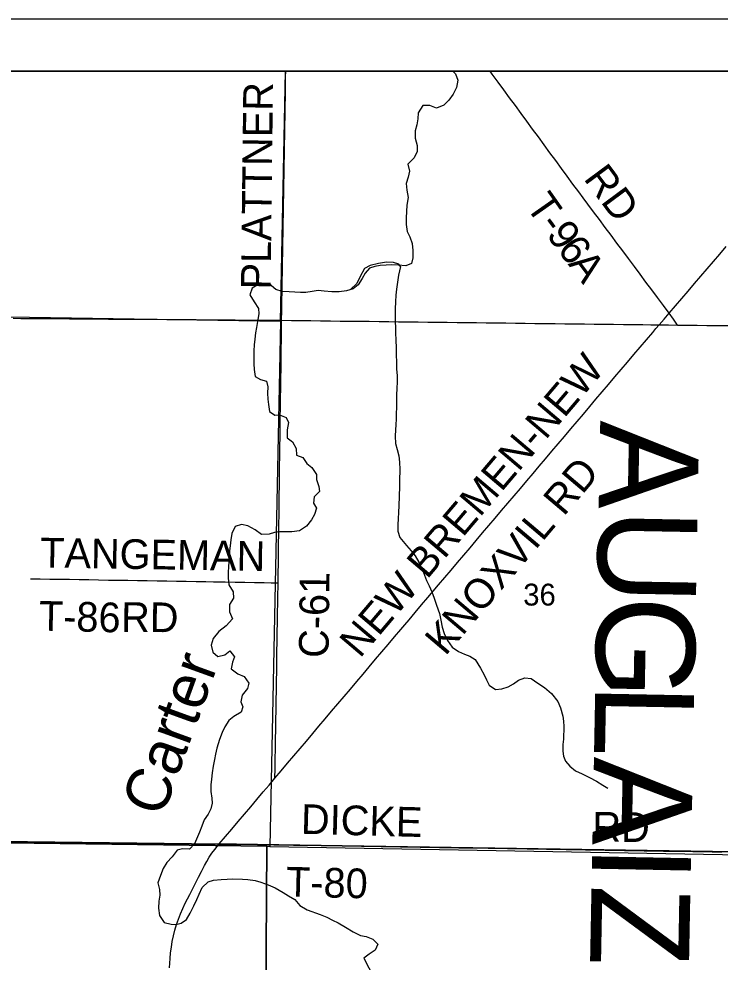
# Model space of a CAD drawing. Extents: x 0 to 34, y 0 to 22.
# Drawn here: x 6.316 to 7.658, y 19.194 to 21 of the extents above; entities that cross this region are included whole.
import ezdxf

# ---------------------------------------------------------------- set-up
doc = ezdxf.new("R2010")
doc.units = 0
for name, color, linetype in [('GM_X_Corporation', 7, 'Continuous'), ('GM_X_County_Road', 7, 'Continuous'), ('GM_X_County_Road_Text', 7, 'Continuous'), ('GM_X_County_Text', 7, 'Continuous'), ('GM_X_Minor_River', 7, 'Continuous'), ('GM_X_Minor_River_Text', 7, 'Continuous'), ('GM_X_Section_Text', 7, 'Continuous'), ('GM_X_Township_Road', 7, 'Continuous'), ('GM_X_Township_Road_Text', 7, 'Continuous'), ('SH_Data', 7, 'Continuous')]:
    doc.layers.add(name, color=color, linetype=linetype)

msp = doc.modelspace()

# ---------------------------------------------------------------- linework, layer by layer
at = {"layer": 'GM_X_Corporation'}
for points in [[(8.9, 20.9), (2.1, 20.9)], [(7.8362, 20.9), (2.1, 20.9)], [(7.8062, 19.1933), (7.8077, 19.2659), (7.8087, 19.3138), (7.8096, 19.3604), (7.8106, 19.4031), (6.935, 19.4163), (6.733, 19.4196), (6.6989, 19.42), (5.8089, 19.4308), (5.2195, 19.4431), (4.8049, 19.4497), (4.7562, 19.4505)], [(5.8089, 19.4308), (6.6989, 19.42), (6.733, 19.4196), (6.935, 19.4163), (7.8106, 19.4031)]]:
    msp.add_lwpolyline(points, dxfattribs=at)
for points in [[(6.8262, 20.9), (5.8246, 20.9), (5.8161, 20.437), (6.817, 20.4215)], [(5.8161, 20.437), (6.817, 20.4215), (6.7967, 19.4154), (6.7907, 19.4159), (5.8008, 19.4289)], [(5.8008, 19.4289), (6.7907, 19.4159), (6.7843, 18.4413), (5.7966, 18.4409)], [(6.7967, 19.4154), (7.8071, 19.3973), (7.7914, 18.4475), (7.7907, 18.396), (6.7843, 18.4413), (6.7907, 19.4159)]]:
    msp.add_lwpolyline(points, close=True, dxfattribs=at)
at = {"layer": 'GM_X_County_Road'}
for points in [[(6.8063, 19.5461), (6.8066, 19.5648), (6.8069, 19.5834), (6.8072, 19.6021), (6.8075, 19.6207), (6.8078, 19.6393), (6.8081, 19.658), (6.8084, 19.6766), (6.8087, 19.6953), (6.809, 19.7139), (6.8093, 19.7325), (6.8096, 19.7512), (6.8099, 19.7698), (6.8102, 19.7885), (6.8105, 19.8071), (6.8108, 19.8257), (6.8111, 19.8444), (6.8114, 19.863), (6.8117, 19.8817), (6.812, 19.9003), (6.8122, 19.9103), (6.8123, 19.9202), (6.8126, 19.9388), (6.8128, 19.9575), (6.8131, 19.9761), (6.8133, 19.9948), (6.8136, 20.0134), (6.8138, 20.032), (6.8141, 20.0507), (6.8143, 20.0693), (6.8146, 20.088), (6.8148, 20.1066), (6.8151, 20.1252), (6.8153, 20.1439), (6.8156, 20.1625), (6.8159, 20.1812), (6.8161, 20.1998), (6.8164, 20.2185), (6.8166, 20.2371), (6.8169, 20.2557), (6.8171, 20.2744), (6.8174, 20.293), (6.8176, 20.3117), (6.8179, 20.3303), (6.8181, 20.3489), (6.8184, 20.3676), (6.8186, 20.3862), (6.8189, 20.4046), (6.8191, 20.4229), (6.8194, 20.4415), (6.8197, 20.4602), (6.82, 20.4788), (6.8204, 20.4975), (6.8207, 20.5161), (6.821, 20.5347), (6.8213, 20.5534), (6.8216, 20.572), (6.8219, 20.5907), (6.8222, 20.6093), (6.8225, 20.628), (6.8228, 20.6466), (6.8231, 20.6652), (6.8235, 20.6839), (6.8238, 20.7025), (6.8241, 20.7212), (6.8244, 20.7398), (6.8247, 20.7584), (6.825, 20.7771), (6.8253, 20.7957), (6.8256, 20.8144), (6.8259, 20.833), (6.8262, 20.8516), (6.8265, 20.8703), (6.8268, 20.8889), (6.827, 20.9)], [(6.6996, 19.4202), (6.7116, 19.4344), (6.7237, 19.4487), (6.7358, 19.4629), (6.7478, 19.4771), (6.7599, 19.4913), (6.7719, 19.5056), (6.784, 19.5198), (6.7951, 19.533), (6.8063, 19.5461), (6.8183, 19.5604), (6.8304, 19.5746), (6.8424, 19.5888), (6.8545, 19.603), (6.8665, 19.6173), (6.8786, 19.6315), (6.8906, 19.6457), (6.9026, 19.66), (6.9147, 19.6742), (6.9267, 19.6884), (6.9388, 19.7027), (6.9508, 19.7169), (6.9628, 19.7311), (6.9749, 19.7453), (6.9869, 19.7596), (6.999, 19.7738), (7.011, 19.788), (7.023, 19.8023), (7.0351, 19.8165), (7.0471, 19.8307), (7.055, 19.84), (7.0629, 19.8494), (7.0749, 19.8636), (7.087, 19.8778), (7.099, 19.8921), (7.1092, 19.9041), (7.1194, 19.9161), (7.1314, 19.9304), (7.1435, 19.9446), (7.1555, 19.9588), (7.1675, 19.973), (7.1796, 19.9873), (7.1916, 20.0015), (7.2037, 20.0157), (7.2157, 20.0299), (7.2278, 20.0442), (7.2398, 20.0584), (7.2519, 20.0726), (7.264, 20.0868), (7.276, 20.101), (7.2881, 20.1153), (7.3001, 20.1295), (7.3122, 20.1437), (7.3242, 20.1579), (7.3363, 20.1722), (7.3483, 20.1864), (7.3604, 20.2006), (7.3724, 20.2148), (7.3845, 20.2291), (7.3965, 20.2433), (7.4086, 20.2575), (7.4206, 20.2717), (7.4327, 20.286), (7.4447, 20.3002), (7.4568, 20.3144), (7.4689, 20.3286), (7.4809, 20.3428), (7.493, 20.3571), (7.505, 20.3713), (7.5171, 20.3855), (7.5291, 20.3997), (7.5352, 20.4069), (7.5413, 20.4141), (7.5511, 20.4252), (7.5608, 20.4363), (7.5729, 20.4505), (7.5851, 20.4646), (7.5972, 20.4788), (7.6093, 20.493), (7.6214, 20.5072), (7.6335, 20.5213), (7.6456, 20.5355), (7.6577, 20.5497), (7.6698, 20.5639)], [(6.6047, 19.1828), (6.6058, 19.2009), (6.6067, 19.2119), (6.6081, 19.2228), (6.6099, 19.2337), (6.6122, 19.2446), (6.6149, 19.2553), (6.618, 19.2659), (6.6216, 19.2763), (6.6256, 19.2866), (6.63, 19.2968), (6.6348, 19.3067), (6.6432, 19.3233), (6.6517, 19.34), (6.6601, 19.3566), (6.6658, 19.3677), (6.6715, 19.3788), (6.6758, 19.3869), (6.6805, 19.3948), (6.6856, 19.4024), (6.691, 19.4098), (6.6996, 19.4202)]]:
    msp.add_lwpolyline(points, dxfattribs=at)
at = {"layer": 'GM_X_Minor_River'}
for points in [[(7.1466, 20.9), (7.1516, 20.8946), (7.1562, 20.8827), (7.1536, 20.8683), (7.1472, 20.8556), (7.1389, 20.8444), (7.1292, 20.8348), (7.1154, 20.8291), (7.1026, 20.834), (7.0893, 20.834), (7.0806, 20.8198), (7.0799, 20.8088), (7.0777, 20.7971), (7.0748, 20.7858), (7.0744, 20.7713), (7.0782, 20.7576), (7.0786, 20.7462), (7.0726, 20.7342), (7.0605, 20.7216), (7.0636, 20.7086), (7.0614, 20.6966), (7.0577, 20.6845), (7.0585, 20.6723), (7.0615, 20.6582)], [(7.0615, 20.6582), (7.0585, 20.6435), (7.0578, 20.6314), (7.0571, 20.6189), (7.0571, 20.606), (7.0594, 20.5926), (7.0641, 20.5826), (7.0687, 20.5696), (7.0702, 20.5563), (7.0702, 20.5423), (7.0676, 20.5313), (7.0565, 20.5274), (7.0418, 20.5282), (7.03, 20.5289), (7.0194, 20.5284), (7.0076, 20.5276), (6.9973, 20.5259), (6.9874, 20.5228), (6.9791, 20.5131), (6.9732, 20.503), (6.9657, 20.4907), (6.956, 20.4834), (6.943, 20.4792), (6.9289, 20.4773), (6.9152, 20.4776), (6.9008, 20.4788), (6.8887, 20.4798), (6.8777, 20.4782), (6.8651, 20.4763), (6.8552, 20.4758), (6.8446, 20.4768), (6.8333, 20.4771), (6.8204, 20.4782), (6.808, 20.4819), (6.795, 20.4925), (6.7851, 20.4935), (6.7756, 20.4919), (6.7625, 20.4846), (6.7584, 20.4715), (6.7668, 20.4584), (6.7748, 20.4452), (6.7756, 20.4354), (6.7734, 20.4244), (6.7708, 20.4089), (6.7693, 20.3987), (6.7679, 20.3866), (6.7665, 20.3756), (6.7658, 20.3643), (6.7658, 20.3506), (6.7659, 20.3396), (6.7667, 20.3286), (6.7683, 20.3153), (6.7784, 20.3097), (6.7904, 20.3063), (6.7924, 20.2956), (6.7921, 20.2831), (6.7926, 20.2721), (6.7938, 20.2615), (6.7957, 20.2481), (6.8058, 20.2414), (6.8153, 20.2419), (6.8277, 20.237), (6.8323, 20.2271), (6.8297, 20.2131), (6.83, 20.1979), (6.8401, 20.19), (6.8469, 20.1773), (6.8478, 20.1648), (6.8598, 20.1599), (6.8674, 20.1487), (6.8771, 20.1409), (6.8859, 20.1278), (6.8856, 20.1183), (6.8902, 20.1049), (6.8918, 20.0953), (6.8813, 20.0846), (6.8798, 20.0729), (6.8857, 20.0629), (6.8823, 20.0512), (6.8763, 20.0411), (6.8665, 20.0285), (6.8534, 20.0197), (6.8386, 20.0178), (6.8283, 20.0177), (6.8154, 20.018), (6.8055, 20.0168), (6.7952, 20.0136), (6.7807, 20.0125), (6.7685, 20.0215), (6.7546, 20.0291), (6.7422, 20.0317), (6.7303, 20.0282), (6.7235, 20.0147), (6.7217, 20.0023), (6.7206, 19.9913), (6.7196, 19.9814), (6.719, 19.9712), (6.7179, 19.9602), (6.7177, 19.9508), (6.717, 19.9405), (6.7167, 19.9295)], [(7.0465, 20.5261), (7.0433, 20.5301), (7.0332, 20.5334), (7.0199, 20.5341), (7.0043, 20.5318), (6.9883, 20.5277), (6.9775, 20.5219), (6.9695, 20.5069), (6.9631, 20.4931), (6.951, 20.482)], [(7.0465, 20.5261), (7.0428, 20.5092), (7.0409, 20.4956), (7.039, 20.4827), (7.0376, 20.471), (7.0369, 20.4585), (7.0365, 20.4449), (7.0366, 20.4319), (7.0366, 20.4202), (7.0371, 20.4092), (7.0372, 20.3989), (7.0376, 20.3845), (7.0383, 20.3704), (7.0384, 20.3575), (7.0387, 20.342), (7.0392, 20.3298), (7.0399, 20.3165), (7.04, 20.3036), (7.0397, 20.2934), (7.0389, 20.2786), (7.039, 20.2661), (7.0382, 20.2342), (7.0375, 20.2225), (7.0368, 20.213), (7.0361, 20.2009), (7.0373, 20.1872), (7.04, 20.1753), (7.0435, 20.1631), (7.0447, 20.1509), (7.0451, 20.1373), (7.0445, 20.116), (7.0446, 20.1046), (7.0436, 20.0678), (7.0429, 20.0553), (7.0418, 20.0425), (7.0415, 20.0319), (7.0416, 20.0193), (7.045, 20.0067), (7.0579, 19.9916), (7.0667, 19.9815), (7.0745, 19.9718), (7.0817, 19.9595), (7.0864, 19.9495), (7.0903, 19.9399), (7.0964, 19.9249), (7.1014, 19.9145), (7.1064, 19.9027), (7.111, 19.8908), (7.1156, 19.8774), (7.1209, 19.8617), (7.1239, 19.8487), (7.1266, 19.8353), (7.1301, 19.8231), (7.1362, 19.8097), (7.1457, 19.7973), (7.1576, 19.7886), (7.1693, 19.7837), (7.179, 19.7797), (7.1895, 19.7734), (7.1997, 19.7568), (7.2065, 19.7441), (7.2108, 19.7345), (7.2162, 19.7241), (7.2286, 19.7162), (7.2407, 19.7174), (7.2526, 19.7209), (7.2626, 19.727), (7.2726, 19.7336), (7.2845, 19.7382), (7.2963, 19.7372), (7.3093, 19.7281), (7.322, 19.7198), (7.3357, 19.7084), (7.3478, 19.6929), (7.3528, 19.6807), (7.3573, 19.6646), (7.3586, 19.6551), (7.3591, 19.6448), (7.3584, 19.6206), (7.3574, 19.6107), (7.3571, 19.5978), (7.3587, 19.5883), (7.3626, 19.5787), (7.3704, 19.569), (7.3815, 19.5604), (7.3942, 19.5543), (7.4085, 19.5475), (7.4216, 19.5404), (7.4339, 19.5328), (7.4436, 19.5269)], [(6.7167, 19.9295), (6.7183, 19.9162), (6.7263, 19.9031), (6.7271, 19.8909), (6.7195, 19.8786), (6.7192, 19.8646), (6.7253, 19.8511), (6.7128, 19.8378), (6.6992, 19.8272), (6.6882, 19.8134), (6.6841, 19.8006), (6.6875, 19.7872), (6.6972, 19.7794), (6.7102, 19.7825), (6.7199, 19.7902), (6.7286, 19.7782), (6.725, 19.768), (6.7227, 19.7552), (6.7354, 19.7461), (6.7474, 19.7409), (6.7565, 19.7281), (6.7536, 19.718), (6.7438, 19.7049), (6.7412, 19.6925), (6.7451, 19.6829), (6.7414, 19.6727), (6.7279, 19.664), (6.7182, 19.6566), (6.7107, 19.6447), (6.7055, 19.6338), (6.7002, 19.6203), (6.6948, 19.6034), (6.6926, 19.5924), (6.6908, 19.5818), (6.6882, 19.569), (6.686, 19.5562), (6.6849, 19.5441), (6.6838, 19.5335), (6.6835, 19.5206), (6.6858, 19.508), (6.6859, 19.4981), (6.6834, 19.4872), (6.6782, 19.4774), (6.6711, 19.4662), (6.6666, 19.4542), (6.6621, 19.4429), (6.6524, 19.4204), (6.643, 19.4104), (6.6294, 19.4108), (6.6195, 19.4084), (6.6096, 19.3957), (6.5995, 19.385), (6.5927, 19.373), (6.5871, 19.3595), (6.5825, 19.346), (6.5856, 19.333), (6.5861, 19.3224), (6.5842, 19.3106), (6.5835, 19.2974), (6.5854, 19.2833), (6.5942, 19.2701), (6.6074, 19.2664), (6.6168, 19.2661), (6.6268, 19.2685), (6.6368, 19.2755), (6.644, 19.2874), (6.6512, 19.3017), (6.6568, 19.314), (6.6612, 19.3242), (6.6669, 19.3369), (6.6786, 19.3476), (6.6889, 19.3508), (6.7033, 19.3519), (6.7147, 19.3531), (6.7242, 19.3533), (6.7443, 19.3527), (6.7546, 19.3521), (6.7685, 19.3502), (6.7791, 19.3469), (6.7934, 19.342), (6.8065, 19.3363), (6.8218, 19.3272), (6.8323, 19.3208), (6.8442, 19.3141), (6.8541, 19.3021), (6.868, 19.2941), (6.8928, 19.2851), (6.9055, 19.2798), (6.9164, 19.2746), (6.9273, 19.269), (6.9415, 19.2611), (6.956, 19.252), (6.9703, 19.2451), (6.9808, 19.243), (6.9936, 19.2381), (7.0032, 19.2283), (6.998, 19.2171), (6.9864, 19.2094), (6.9767, 19.2013), (7.0145, 19.1272)]]:
    msp.add_lwpolyline(points, dxfattribs=at)
at = {"layer": 'GM_X_Township_Road'}
for points in [[(7.5768, 20.4137), (7.5688, 20.425), (7.5608, 20.4363), (7.5497, 20.4512), (7.5385, 20.4662), (7.5274, 20.4811), (7.5162, 20.4961), (7.5051, 20.511), (7.494, 20.526), (7.4828, 20.5409), (7.4717, 20.5558), (7.4605, 20.5708), (7.4494, 20.5857), (7.4382, 20.6007), (7.4271, 20.6156), (7.4159, 20.6306), (7.4048, 20.6455), (7.3962, 20.6571), (7.3875, 20.6686), (7.3765, 20.6836), (7.3655, 20.6987), (7.3545, 20.7137), (7.3435, 20.7288), (7.3324, 20.7438), (7.3214, 20.7588), (7.3104, 20.7739), (7.2994, 20.7889), (7.2883, 20.8039), (7.2773, 20.819), (7.2663, 20.834), (7.2553, 20.8491), (7.2442, 20.8641), (7.2332, 20.8791), (7.2222, 20.8942), (7.2179, 20.9)], [(6.3054, 20.4269), (6.3198, 20.4266), (6.3385, 20.4264), (6.3571, 20.4263), (6.3758, 20.4262), (6.3944, 20.426), (6.413, 20.4259), (6.4317, 20.4257), (6.4503, 20.4256), (6.469, 20.4255), (6.4876, 20.4253), (6.5062, 20.4252), (6.5249, 20.4251), (6.5435, 20.4249), (6.5622, 20.4248), (6.5808, 20.4247), (6.5994, 20.4245), (6.6181, 20.4244), (6.6367, 20.4242), (6.6554, 20.4241), (6.674, 20.424), (6.6927, 20.4238), (6.7113, 20.4237), (6.7299, 20.4236), (6.7486, 20.4234), (6.7672, 20.4233), (6.7859, 20.4231), (6.8025, 20.423), (6.8191, 20.4229), (6.8378, 20.4227), (6.8564, 20.4225), (6.875, 20.4222), (6.8937, 20.422), (6.9123, 20.4218), (6.931, 20.4215), (6.9496, 20.4213), (6.9682, 20.4211), (6.9869, 20.4209), (7.0055, 20.4206), (7.0242, 20.4204), (7.0428, 20.4202), (7.0614, 20.42), (7.0801, 20.4197), (7.0987, 20.4195), (7.1174, 20.4193), (7.136, 20.4191), (7.1547, 20.4188), (7.1733, 20.4186), (7.1919, 20.4184), (7.2106, 20.4181), (7.2292, 20.4179), (7.2479, 20.4177), (7.2665, 20.4175), (7.2851, 20.4172), (7.3038, 20.417), (7.3138, 20.4169), (7.3239, 20.4168), (7.3425, 20.4165), (7.3612, 20.4163), (7.3798, 20.4161), (7.3985, 20.4159), (7.4171, 20.4156), (7.4357, 20.4154), (7.4544, 20.4152), (7.473, 20.415), (7.4917, 20.4147), (7.5103, 20.4145), (7.5258, 20.4143), (7.5413, 20.4141)], [(7.5413, 20.4141), (7.5591, 20.4139), (7.5768, 20.4137), (7.5955, 20.4135), (7.6141, 20.4133), (7.6327, 20.4132), (7.6514, 20.413), (7.67, 20.4128), (7.6887, 20.4126), (7.7073, 20.4125), (7.7259, 20.4123), (7.7446, 20.4121), (7.7632, 20.4119), (7.7819, 20.4117), (7.8005, 20.4116), (7.8153, 20.4114), (7.8301, 20.4113)], [(6.3384, 19.9281), (6.3571, 19.9278), (6.3757, 19.9275), (6.3943, 19.9272), (6.413, 19.9269), (6.4316, 19.9266), (6.4503, 19.9263), (6.4689, 19.926), (6.4876, 19.9256), (6.5062, 19.9253), (6.5248, 19.925), (6.5435, 19.9247), (6.5621, 19.9244), (6.5808, 19.9241), (6.5994, 19.9238), (6.618, 19.9235), (6.6367, 19.9232), (6.6553, 19.9228), (6.674, 19.9225), (6.6885, 19.9223)], [(6.6885, 19.9223), (6.6926, 19.9222), (6.7112, 19.9219), (6.7299, 19.9216), (6.7485, 19.9213), (6.7672, 19.921), (6.7858, 19.9206), (6.7991, 19.9204), (6.8123, 19.9202)], [(6.6996, 19.4202), (6.7182, 19.42), (6.7369, 19.4197), (6.7555, 19.4195), (6.7742, 19.4192), (6.7892, 19.419), (6.8043, 19.4188), (6.8229, 19.4185), (6.8415, 19.4182), (6.8602, 19.4179), (6.8788, 19.4176), (6.8975, 19.4173), (6.9161, 19.417), (6.9347, 19.4167), (6.9534, 19.4164), (6.972, 19.4161), (6.9907, 19.4158), (7.0093, 19.4155), (7.028, 19.4152), (7.0466, 19.4149), (7.0652, 19.4146), (7.0839, 19.4143), (7.1025, 19.414), (7.1212, 19.4137), (7.1398, 19.4134), (7.1584, 19.4131), (7.1771, 19.4128), (7.1957, 19.4125), (7.2144, 19.4122), (7.233, 19.4119), (7.2516, 19.4116), (7.2703, 19.4113), (7.2889, 19.411), (7.3076, 19.4107), (7.3262, 19.4104), (7.3448, 19.4101), (7.3635, 19.4098), (7.3821, 19.4095), (7.4008, 19.4091), (7.4194, 19.4088), (7.4381, 19.4085), (7.4567, 19.4082), (7.4753, 19.4079), (7.494, 19.4076), (7.5126, 19.4073), (7.5313, 19.407), (7.5499, 19.4067), (7.5685, 19.4064), (7.5872, 19.4061), (7.6058, 19.4058), (7.6245, 19.4055), (7.6431, 19.4052), (7.6617, 19.4049)]]:
    msp.add_lwpolyline(points, dxfattribs=at)
at = {"layer": 'SH_Data'}
for p, q in [((2, 21), (9, 21)), ((2.1, 20.9), (8.9, 20.9)), ((2.1, 20.9), (8.9, 20.9))]:
    msp.add_line(p, q, dxfattribs=at)

# ---------------------------------------------------------------- texts
at = {"layer": 'GM_X_County_Road_Text'}
for s, height, rotation, p in [('PLATTNER', 0.05682, 89.3277, (6.798, 20.4817)), ('NEW BREMEN-NEW', 0.056818, 49.6467, (6.9689, 19.7744)), ('KNOXVIL RD', 0.05682, 49.7166, (7.1322, 19.7787)), ('C-61', 0.05682, 89.3136, (6.9088, 19.7762))]:
    msp.add_text(s, height=height, rotation=rotation, dxfattribs=at).set_placement(p)
at = {"layer": 'GM_X_County_Text'}
for s, rotation, p in [('A', 268.931, (7.4288, 20.2314)), ('U', 268.9294, (7.4257, 20.0639)), ('G', 268.9267, (7.4226, 19.8964)), ('L', 268.9212, (7.4194, 19.729)), ('A', 268.9071, (7.4168, 19.5874)), ('I', 268.8989, (7.4136, 19.4199)), ('Z', 268.909, (7.4121, 19.3424))]:
    msp.add_text(s, height=0.1894, rotation=rotation, dxfattribs=at).set_placement(p)
at = {"layer": 'GM_X_Minor_River_Text'}
msp.add_text('Carter', height=0.08523, rotation=70.026, dxfattribs=at).set_placement((6.591, 19.4691))
at = {"layer": 'GM_X_Section_Text'}
msp.add_text('36', height=0.04186, rotation=0, dxfattribs=at).set_placement((7.2814, 19.8767))
at = {"layer": 'GM_X_Township_Road_Text'}
for s, height, rotation, p in [('RD', 0.05682, 306.573, (7.3956, 20.6941)), ('T', 0.0568, 305.1082, (7.2849, 20.6416)), ('-', 0.0568, 306.4247, (7.3102, 20.6057)), ('9', 0.0568, 306.6469, (7.3242, 20.5867)), ('6', 0.0568, 306.731, (7.3451, 20.5585)), ('A', 0.0568, 306.751, (7.3661, 20.5305)), ('TANGEMAN', 0.05682, 359.041, (6.3568, 19.9498)), ('T-86', 0.05682, 358.6533, (6.3541, 19.8288)), ('RD', 0.05682, 359.5064, (6.5118, 19.8264)), ('DICKE', 0.05682, 358.4279, (6.8555, 19.4398)), ('RD', 0.05682, 359.5064, (7.4136, 19.4248)), ('T-80', 0.05682, 358.6026, (6.827, 19.3197))]:
    msp.add_text(s, height=height, rotation=rotation, dxfattribs=at).set_placement(p)

doc.saveas('drawing.dxf')
